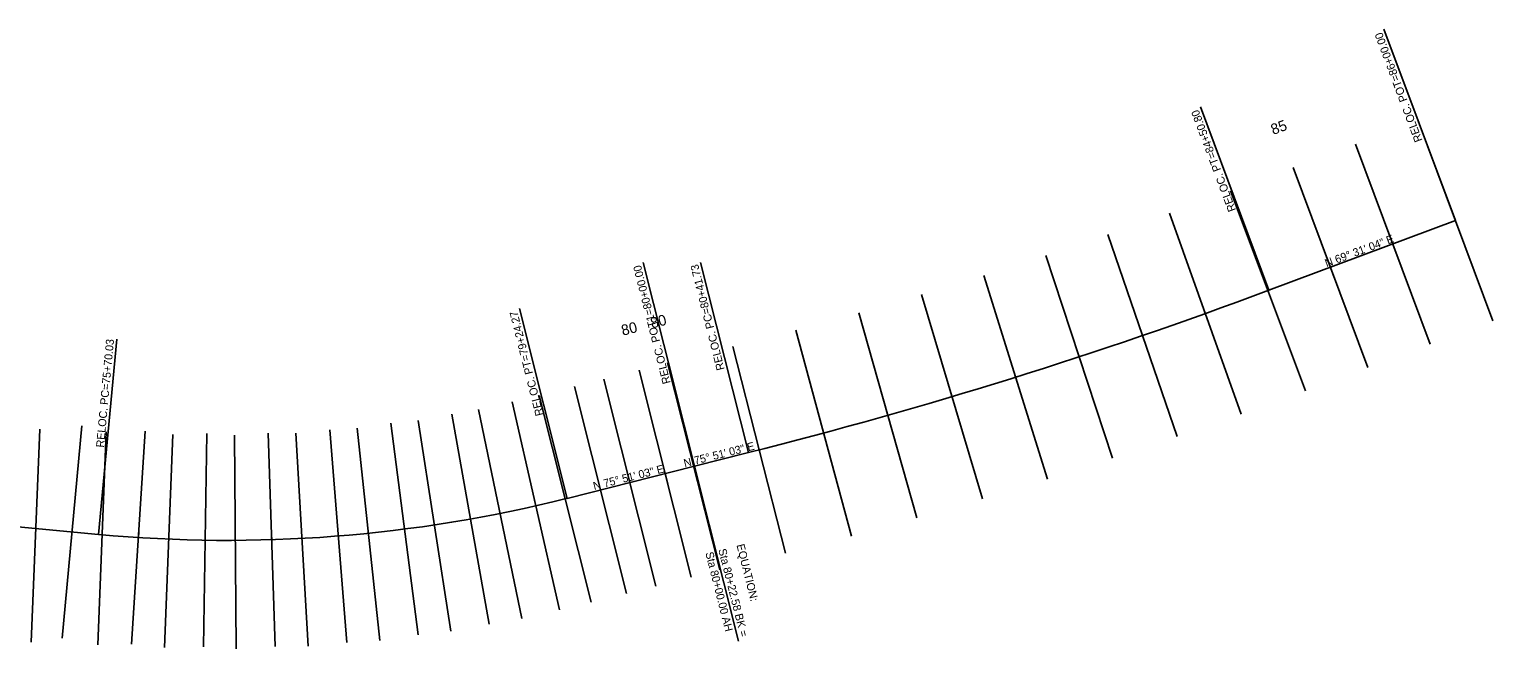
# Model space of a CAD drawing. Extents: x 1965757 to 1970272, y 1117058 to 1118406.
# Drawn here: x 1969174 to 1970272, y 1117804 to 1118269 of the extents above; entities that cross this region are included whole.
import ezdxf

# ---------------------------------------------------------------- set-up
doc = ezdxf.new("R2010")
doc.units = 0
for name, color, linetype in [('RD_HC_CL_Rel', 7, 'Continuous'), ('RD_HC_Data_Rel', 7, 'Continuous'), ('RD_HC_Data_Tic_Rel', 7, 'Continuous'), ('RD_HC_TX_Rel_Sta50', 7, 'Continuous'), ('RD_PD_PatLn1', 7, 'Continuous'), ('RD_PD_PatLn2', 7, 'Continuous')]:
    doc.layers.add(name, color=color, linetype=linetype)

msp = doc.modelspace()

# ---------------------------------------------------------------- linework, layer by layer
at = {"layer": 'RD_HC_CL_Rel'}
for p, q in [((1970104, 1118072.9), (1970243.8, 1118125.1)), ((1968277.4, 1117978.5), (1969226.4, 1117889.9)), ((1969673.3, 1117941), (1969713.7, 1117951.2)), ((1969577.9, 1117916.9), (1969673.3, 1117941))]:
    msp.add_line(p, q, dxfattribs=at)
for centre, radius, start, end in [((1968809, 1121539.8), 3700.9, 284.1493, 290.4823), ((1969323.3, 1118927.1), 1041.7, 264.6661, 284.1493)]:
    msp.add_arc(centre, radius, start, end, dxfattribs=at)
at = {"layer": 'RD_HC_Data_Rel'}
for p, q in [((1970243.8, 1118125.1), (1970190.2, 1118268.6)), ((1970104, 1118072.9), (1970052.7, 1118210.4)), ((1969673.3, 1117941), (1969634.7, 1118093.8)), ((1969713.7, 1117951.2), (1969677.8, 1118093.7)), ((1969577.9, 1117916.9), (1969542, 1118059.3)), ((1969226.4, 1117889.9), (1969240.1, 1118036.2)), ((1969673.3, 1117941), (1969706.3, 1117809.9))]:
    msp.add_line(p, q, dxfattribs=at)
at = {"layer": 'RD_HC_Data_Tic_Rel'}
for p, q in [((1970150.1, 1118090.1), (1970147.3, 1118097.6)), ((1970150.1, 1118090.1), (1970152.9, 1118082.6)), ((1970056.3, 1118055.4), (1970055, 1118059.2)), ((1969961.7, 1118023), (1969960.5, 1118026.8)), ((1969866.3, 1117993.1), (1969865.2, 1117997)), ((1969770.1, 1117965.9), (1969769.1, 1117969.7)), ((1969673.3, 1117941), (1969671.3, 1117948.7)), ((1969651.4, 1117935.5), (1969649.4, 1117943.2)), ((1969651.4, 1117935.5), (1969653.3, 1117927.7)), ((1969673.3, 1117941), (1969675.2, 1117933.2)), ((1969554.3, 1117911.3), (1969553.4, 1117915.2)), ((1969256.3, 1117887.5), (1969256.6, 1117891.5)), ((1969356.3, 1117885.9), (1969356.1, 1117889.9)), ((1969455.9, 1117893.8), (1969455.4, 1117897.8))]:
    msp.add_line(p, q, dxfattribs=at)
at = {"layer": 'RD_PD_PatLn1'}
for p, q in [((1970215.8, 1118200), (1970271.8, 1118050.1)), ((1970169, 1118182.5), (1970225, 1118032.6)), ((1970122.1, 1118165), (1970178.1, 1118015.1)), ((1970075.3, 1118147.5), (1970131.3, 1117997.6)), ((1970029.4, 1118130.7), (1970083.3, 1117980.1)), ((1969983.2, 1118114.6), (1970035.1, 1117963.2)), ((1969936.8, 1118099), (1969986.7, 1117947)), ((1969890.2, 1118084.1), (1969938, 1117931.4)), ((1969843.5, 1118069.8), (1969889.2, 1117916.5)), ((1969796.5, 1118056.1), (1969840.1, 1117902.2)), ((1969749.3, 1118043.1), (1969790.9, 1117888.6)), ((1969702, 1118030.7), (1969741.5, 1117875.7)), ((1969653.7, 1118018.6), (1969692.8, 1117863.4)), ((1969605.2, 1118006.3), (1969644.3, 1117851.2)), ((1969556.7, 1117994.1), (1969595.8, 1117839)), ((1969511.4, 1117983.6), (1969543.7, 1117826.9)), ((1969182.3, 1117968.9), (1969175.9, 1117809)), ((1969232.2, 1117966.9), (1969225.9, 1117807)), ((1969374.4, 1117965.7), (1969383.6, 1117806)), ((1969420.3, 1117969.5), (1969437.3, 1117810.4)), ((1969466.1, 1117975.4), (1969490.7, 1117817.3)), ((1969282.2, 1117964.9), (1969275.8, 1117805)), ((1969328.3, 1117964.2), (1969329.7, 1117804.2))]:
    msp.add_line(p, q, dxfattribs=at)
at = {"layer": 'RD_PD_PatLn2'}
for p, q in [((1970215.8, 1118200), (1970271.8, 1118050.1)), ((1970169, 1118182.5), (1970225, 1118032.6)), ((1970122.1, 1118165), (1970178.1, 1118015.1)), ((1970075.3, 1118147.5), (1970131.3, 1117997.6)), ((1970029.4, 1118130.7), (1970083.3, 1117980.1)), ((1969983.2, 1118114.6), (1970035.1, 1117963.2)), ((1969936.8, 1118099), (1969986.7, 1117947)), ((1969890.2, 1118084.1), (1969938, 1117931.4)), ((1969843.5, 1118069.8), (1969889.2, 1117916.5)), ((1969796.5, 1118056.1), (1969840.1, 1117902.2)), ((1969749.3, 1118043.1), (1969790.9, 1117888.6)), ((1969702, 1118030.7), (1969741.5, 1117875.7)), ((1969631.8, 1118013), (1969670.9, 1117857.9)), ((1969653.1, 1118018.4), (1969692.2, 1117863.3)), ((1969653.7, 1118018.6), (1969692.8, 1117863.4)), ((1969583.3, 1118000.8), (1969622.4, 1117845.7)), ((1969536.6, 1117989.3), (1969572.1, 1117833.3)), ((1969491.3, 1117980.1), (1969519.3, 1117822.6)), ((1969213.9, 1117971.4), (1969199.1, 1117812.1)), ((1969261.5, 1117967.3), (1969251.2, 1117807.7)), ((1969307.6, 1117965.5), (1969305, 1117805.5)), ((1969353.7, 1117965.8), (1969358.8, 1117805.9)), ((1969399.8, 1117968.4), (1969412.5, 1117808.9)), ((1969445.7, 1117973.2), (1969466.1, 1117814.5))]:
    msp.add_line(p, q, dxfattribs=at)

# ---------------------------------------------------------------- texts
at = {"layer": 'RD_HC_Data_Rel'}
for s, rotation, p in [('RELOC. POT=86+00.00', 110.4823, (1970219.2, 1118185.3)), ('RELOC. PT=84+50.80', 110.4823, (1970079.4, 1118133.1)), ('N 69%%d 31\' 04" E', 20.4823, (1970147.3, 1118090.1)), ('RELOC. POT1=80+00.00', 104.1493, (1969655.4, 1118003.5)), ('RELOC. PC=80+41.73', 104.1493, (1969695.9, 1118013.7)), ('RELOC. PT=79+24.27', 104.1493, (1969560.1, 1117979.5)), ('RELOC. PC=75+70.03', 84.6661, (1969230.5, 1117954.8)), ('N 75%%d 51\' 03" E', 14.1493, (1969666, 1117940.2)), ('N 75%%d 51\' 03" E', 14.1493, (1969598.1, 1117923.1)), ('Sta 80+22.58 BK = ', 284.1493, (1969691.1, 1117878.4)), ('EQUATION:', 284.1493, (1969704.7, 1117881.9)), ('Sta 80+00.00 AH', 284.1493, (1969681.4, 1117876))]:
    msp.add_text(s, height=6, rotation=rotation, dxfattribs=at).set_placement(p)
at = {"layer": 'RD_HC_TX_Rel_Sta50'}
for s, rotation, p in [('85', 20.4823, (1970107.2, 1118189.3)), ('80', 14.1493, (1969641.4, 1118044.3)), ('80', 14.1493, (1969619.5, 1118038.8))]:
    msp.add_text(s, height=8, rotation=rotation, dxfattribs=at).set_placement(p)

doc.saveas('drawing.dxf')
